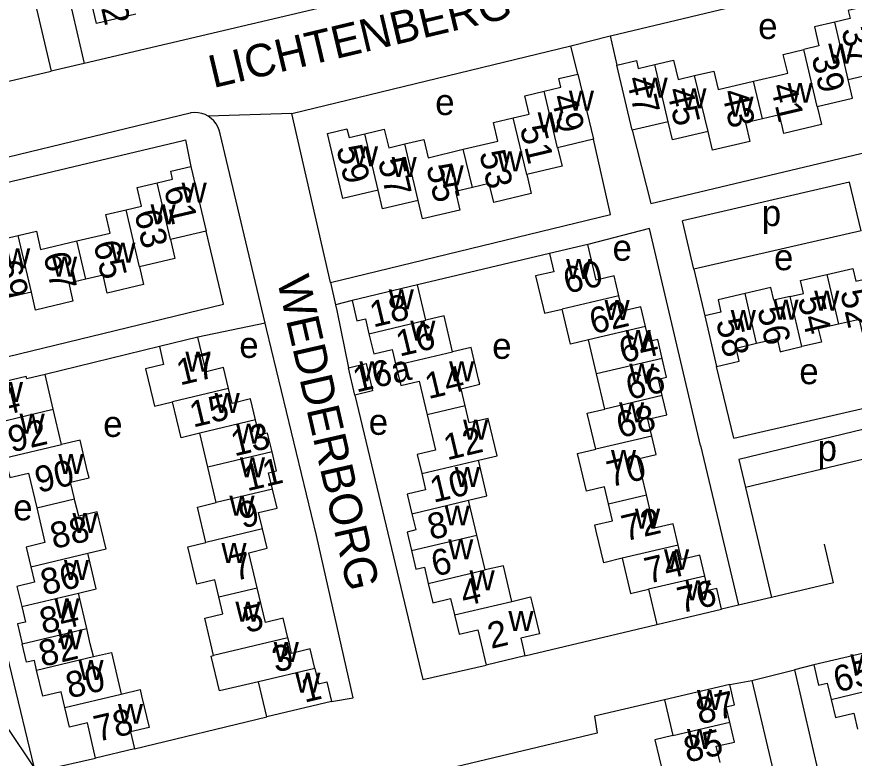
# Model space of a CAD drawing. Extents: x 157646 to 159241, y 379213 to 381217.
# Drawn here: x 158882.3 to 159011, y 380482.4 to 380596.4 of the extents above; entities that cross this region are included whole.
import ezdxf

# ---------------------------------------------------------------- set-up
doc = ezdxf.new("R2010")
doc.units = 0
for name, color, linetype in [('BLT_Basislijn', 7, 'Continuous'), ('BLT_Bebouwing', 7, 'Continuous'), ('BLT_Centroide', 7, 'Continuous'), ('BLT_Huisnummer', 7, 'Continuous'), ('BLT_Huisnummer_ tussenligend', 7, 'Continuous'), ('BLT_Onderverdeling_panden', 7, 'Continuous'), ('BLT_Straatnaam', 7, 'Continuous'), ('BLT_Vlakafsluiter', 7, 'Continuous')]:
    doc.layers.add(name, color=color, linetype=linetype)

msp = doc.modelspace()

# ---------------------------------------------------------------- linework, layer by layer
at = {"layer": 'BLT_Basislijn'}
for p, q in [((158877.56, 380630.67), (158887.56, 380588.05)), ((158890.7, 380597.66), (158892.65, 380589.24)), ((158931.2, 380598.31), (158892.65, 380589.24)), ((158967.46, 380591.96), (158973.51, 380593.48)), ((158973.51, 380593.48), (158974.53, 380588.98)), ((158968.54, 380587.61), (158967.46, 380591.96)), ((158892.65, 380589.24), (158887.56, 380588.05)), ((158865.01, 380582.73), (158887.56, 380588.05)), ((158908.94, 380581.61), (158855.86, 380568.7)), ((158920.46, 380549.28), (158913.52, 380578.44)), ((158908.19, 380577.48), (158909.04, 380573.42)), ((159010.31, 380570.97), (158984.61, 380565.02)), ((159012.09, 380563.48), (159010.31, 380570.97)), ((158986.36, 380557.62), (158984.61, 380565.02)), ((158964.16, 380560.01), (158943.87, 380555.18)), ((158930.51, 380555.55), (158931.28, 380552.13)), ((158933.81, 380552.79), (158931.28, 380552.13)), ((158920.46, 380549.28), (158910.12, 380547.13)), ((158904.19, 380545.72), (158886.63, 380541.42)), ((158992.48, 380531.61), (158989.86, 380542.66)), ((159017.31, 380534.13), (158993.25, 380528.36)), ((158987.39, 380530.49), (158993.2, 380505.92)), ((159018.36, 380529.81), (158994.28, 380524.03)), ((158993.25, 380528.36), (158994.28, 380524.03)), ((158994.28, 380524.03), (158998.29, 380507.12)), ((159007.83, 380509.38), (159006.42, 380515.34)), ((158993.2, 380505.92), (158990.63, 380505.31)), ((158960.4, 380498.13), (158980.68, 380502.96)), ((158944.72, 380494.53), (158954.44, 380496.71)), ((159004.81, 380496.74), (159001.81, 380495.97)), ((158995.27, 380494.34), (159001.81, 380495.97)), ((159001.81, 380495.97), (159010.79, 380457.61)), ((158991.88, 380493.75), (158995.27, 380494.34)), ((158995.27, 380494.34), (159004.29, 380456.24)), ((158900.37, 380483.84), (158920.71, 380488.74))]:
    msp.add_line(p, q, dxfattribs=at)
for points in [[(158973.51, 380593.48), (158973.74, 380593.53), (159014.59, 380603.35)], [(158976.89, 380578.97), (158979.77, 380567.69), (159056.36, 380585.97), (159053.88, 380597.08)], [(158924.54, 380581.53), (158967.46, 380591.96)], [(158911.72, 380581.12), (158911.23, 380581.38), (158910.71, 380581.56), (158910.16, 380581.66), (158909.61, 380581.69), (158909.05, 380581.63), (158908.94, 380581.61)], [(158913.52, 380578.44), (158913.4, 380578.98), (158913.19, 380579.5), (158912.92, 380579.98), (158912.58, 380580.42), (158912.18, 380580.8), (158911.72, 380581.12)], [(158930.51, 380555.55), (158924.54, 380581.53)], [(158838.2, 380560.85), (158907.85, 380577.41), (158908.19, 380577.48)], [(158930.51, 380555.55), (158973.55, 380566), (158970.92, 380577.58)], [(158987.39, 380530.49), (158979.54, 380563.84), (158970.05, 380561.41)], [(158865.95, 380540.53), (158914.06, 380552.25), (158911.37, 380563.45)], [(159012.09, 380563.48), (158986.36, 380557.62)], [(158986.36, 380557.62), (158988.06, 380550.41)], [(158931.28, 380552.13), (158931.48, 380551.25), (158933.26, 380542.46)], [(158930.66, 380491.12), (158933.99, 380491.67), (158928.35, 380516.64), (158920.66, 380548.44), (158920.46, 380549.28)], [(158934.26, 380538.23), (158944.72, 380494.53)], [(158992.48, 380531.61), (159016.74, 380537.19), (159018.05, 380537.49)], [(158877.97, 380509.59), (158884.88, 380481.07)], [(159007.83, 380509.38), (158998.29, 380507.12)], [(158998.29, 380507.12), (158993.2, 380505.92)], [(158884.88, 380481.07), (158872.72, 380499.22)], [(158981.85, 380491.39), (158971.06, 380488.87), (158971.5, 380486.26), (158925.77, 380475.35), (158905.24, 380470.64), (158904.26, 380470.56), (158903.54, 380472.61), (158902.77, 380472.58), (158881.56, 380467.45)], [(158884.88, 380481.07), (158885.27, 380480.69), (158886.62, 380480.68), (158894.4, 380482.43)]]:
    msp.add_lwpolyline(points, dxfattribs=at)
at = {"layer": 'BLT_Bebouwing'}
for p, q in [((158976.89, 380578.97), (158974.53, 380588.98)), ((158968.54, 380587.61), (158970.92, 380577.58)), ((159010.1, 380586.76), (159015.43, 380588.01)), ((158982.41, 380580.27), (158976.89, 380578.97)), ((158970.92, 380577.58), (158965.42, 380576.28)), ((158909.04, 380573.42), (158911.37, 380563.45)), ((158911.37, 380563.45), (158905.89, 380562.16)), ((158970.05, 380561.41), (158964.16, 380560.01)), ((158943.87, 380555.18), (158933.81, 380552.79)), ((158945.16, 380549.75), (158943.87, 380555.18)), ((158988.06, 380550.41), (158989.86, 380542.66)), ((158910.12, 380547.13), (158904.19, 380545.72)), ((158971.4, 380541.5), (158970.16, 380546.72)), ((158934.26, 380538.23), (158933.26, 380542.46)), ((158887.88, 380536.08), (158886.63, 380541.42)), ((158972.68, 380536.1), (158971.4, 380541.5)), ((158911.64, 380527.15), (158910.39, 380532.37)), ((158912.94, 380521.71), (158911.64, 380527.15)), ((158953.02, 380516.71), (158951.74, 380522.08)), ((158954.29, 380511.35), (158953.02, 380516.71)), ((158979.4, 380508.38), (158980.68, 380502.96)), ((158893.03, 380502.34), (158891.74, 380507.79)), ((158980.68, 380502.96), (158990.63, 380505.31)), ((158960.4, 380498.13), (158954.44, 380496.71)), ((159014.74, 380499.09), (159004.81, 380496.74)), ((158920.71, 380488.74), (158919.42, 380494.13)), ((158991.88, 380493.75), (158981.85, 380491.39)), ((158930.66, 380491.12), (158920.71, 380488.74)), ((158981.85, 380491.39), (158983.14, 380485.9)), ((158900.37, 380483.84), (158894.4, 380482.43))]:
    msp.add_line(p, q, dxfattribs=at)
for points in [[(158900.58, 380596.82), (158894.54, 380595.38), (158893.82, 380598.4), (158890.7, 380597.66)], [(159013.07, 380598.07), (159010.09, 380597.37), (159010.38, 380596.15), (159008.02, 380595.59)], [(159008.02, 380595.59), (159004.89, 380594.86), (159005.58, 380591.93), (159003.26, 380591.38)], [(158995.54, 380586.52), (159000, 380587.57), (159000.79, 380587.75), (159000.11, 380590.64), (159003.26, 380591.38)], [(158974.53, 380588.98), (158977.53, 380589.69), (158977.82, 380588.48), (158980.34, 380589.07)], [(158980.34, 380589.07), (158983.24, 380589.75), (158983.94, 380586.78), (158986.46, 380587.37)], [(158963.36, 380584.98), (158965.9, 380585.58), (158965.59, 380586.91), (158968.54, 380587.61)], [(158986.46, 380587.37), (158989.41, 380588.07), (158990.08, 380585.23), (158995.54, 380586.52)], [(159005.32, 380582.62), (159010.77, 380583.91), (159010.1, 380586.76)], [(158958.6, 380580.88), (158961.05, 380581.46), (158960.38, 380584.27), (158963.36, 380584.98)], [(159005.32, 380582.62), (159005.97, 380579.85), (159000.18, 380578.49), (158999.98, 380579.38), (158999.52, 380581.33), (158996.9, 380580.71)], [(158950.92, 380576.04), (158956.23, 380577.29), (158955.55, 380580.15), (158958.6, 380580.88)], [(158996.9, 380580.71), (158994.28, 380580.09), (158994.95, 380577.24), (158989.22, 380575.89), (158988.54, 380578.77)], [(158937.84, 380569.76), (158932.4, 380568.47), (158930.03, 380578.48), (158933.03, 380579.19), (158933.35, 380577.86), (158935.79, 380578.43)], [(158935.79, 380578.43), (158938.77, 380579.14), (158939.45, 380576.29), (158941.93, 380576.87)], [(158988.54, 380578.77), (158983.06, 380577.48), (158982.41, 380580.27)], [(158941.93, 380576.87), (158944.84, 380577.56), (158945.5, 380574.75), (158950.92, 380576.04)], [(158965.42, 380576.28), (158966.09, 380573.45), (158960.66, 380572.16)], [(158903.85, 380570.9), (158906.22, 380571.46), (158905.93, 380572.7), (158909.04, 380573.42)], [(158960.66, 380572.16), (158961.35, 380569.23), (158955.6, 380567.87), (158954.91, 380570.79), (158952.31, 380570.18)], [(158899.07, 380566.75), (158901.45, 380567.31), (158900.77, 380570.18), (158903.85, 380570.9)], [(158952.31, 380570.18), (158949.71, 380569.56), (158950.39, 380566.69), (158944.66, 380565.34), (158943.99, 380568.17)], [(158943.99, 380568.17), (158938.52, 380566.88), (158937.84, 380569.76)], [(158891.52, 380561.94), (158896.65, 380563.15), (158895.98, 380566.03), (158899.07, 380566.75)], [(158876.43, 380564.33), (158879.16, 380564.97), (158879.81, 380562.15), (158882.49, 380562.78)], [(158882.49, 380562.78), (158885.28, 380563.43), (158885.94, 380560.64), (158891.52, 380561.94)], [(158905.89, 380562.16), (158906.57, 380559.25), (158901.12, 380557.97)], [(158974.81, 380553.53), (158974.09, 380556.59), (158971.34, 380555.93), (158970.05, 380561.41)], [(158964.16, 380560.01), (158964.82, 380557.22), (158962.04, 380556.56), (158963.19, 380551.69), (158963.39, 380550.83), (158966.13, 380551.48)], [(158901.12, 380557.97), (158901.76, 380555.24), (158896.18, 380553.93), (158895.54, 380556.69), (158892.9, 380556.07)], [(159006.79, 380556.8), (159010.81, 380557.73), (159011.27, 380555.77), (159013.76, 380556.35)], [(158892.9, 380556.07), (158890.26, 380555.46), (158890.91, 380552.67), (158885.17, 380551.32), (158884.52, 380554.08)], [(159001.17, 380553.42), (159003.22, 380553.89), (159002.76, 380555.87), (159006.79, 380556.8)], [(158884.52, 380554.08), (158879.12, 380552.82), (158878.47, 380555.62)], [(159001.17, 380553.42), (159000, 380553.15), (158998.63, 380552.83), (158998.17, 380554.79), (158994.23, 380553.87)], [(158978.95, 380548.8), (158978.23, 380551.81), (158975.38, 380551.13), (158974.81, 380553.53)], [(158994.23, 380553.87), (158990.08, 380552.9), (158990.53, 380550.99), (158988.06, 380550.41)], [(158933.81, 380552.79), (158934.55, 380549.68), (158935.86, 380549.99), (158936.41, 380547.67)], [(158970.16, 380546.72), (158967.41, 380546.07), (158966.13, 380551.48)], [(158949.27, 380544.9), (158947.96, 380550.41), (158945.16, 380549.75)], [(159015.54, 380548.65), (159012.26, 380547.89), (159011.8, 380549.88), (159008.57, 380549.13)], [(158981.49, 380543.89), (158980.8, 380546.79), (158979.49, 380546.48), (158978.95, 380548.8)], [(159008.57, 380549.13), (159005.49, 380548.42), (159005.96, 380546.4), (159002.98, 380545.7)], [(158914.83, 380539.25), (158914.06, 380542.48), (158911.39, 380541.84), (158910.12, 380547.13)], [(158936.41, 380547.67), (158937.15, 380544.58), (158939.98, 380545.26), (158940.55, 380542.83)], [(158996.01, 380546.22), (158999.18, 380546.96), (158999.65, 380544.92), (159000, 380545), (159002.98, 380545.7)], [(158904.19, 380545.72), (158904.85, 380542.95), (158902.06, 380542.28), (158903.22, 380537.42), (158903.43, 380536.53), (158906.21, 380537.19)], [(158989.86, 380542.66), (158993.32, 380543.47), (158992.85, 380545.48), (158996.01, 380546.22)], [(158951.2, 380536.59), (158950.57, 380539.22), (158953.45, 380539.9), (158953.26, 380540.71), (158952.1, 380545.57), (158949.27, 380544.9)], [(158933.26, 380542.46), (158935.98, 380543.1), (158936.98, 380538.88), (158934.26, 380538.23)], [(158981.51, 380538.19), (158980.92, 380540.69), (158982.17, 380540.99), (158981.49, 380543.89)], [(158940.55, 380542.83), (158941.29, 380539.72), (158944.12, 380540.39), (158945.35, 380535.2)], [(158886.63, 380541.42), (158883.81, 380540.76), (158883.73, 380541.08), (158873.59, 380538.7)], [(158918.99, 380534.43), (158918.22, 380537.65), (158915.37, 380536.97), (158914.83, 380539.25)], [(158979.91, 380531.94), (158979.3, 380534.53), (158982.21, 380535.22), (158981.51, 380538.19)], [(158910.39, 380532.37), (158907.52, 380531.69), (158906.21, 380537.19)], [(158953.23, 380528.23), (158956.1, 380528.91), (158954.73, 380534.66), (158951.82, 380533.96), (158951.2, 380536.59)], [(158889.17, 380530.62), (158887.88, 380536.08)], [(158971.29, 380529.91), (158969.98, 380535.46), (158972.68, 380536.1)], [(158921.51, 380529.5), (158920.81, 380532.41), (158919.54, 380532.11), (158918.99, 380534.43)], [(158945.35, 380535.2), (158946.64, 380529.78), (158943.83, 380529.11), (158944.53, 380526.16)], [(158979.07, 380522.91), (158977.76, 380528.42), (158980.58, 380529.09), (158979.91, 380531.94)], [(158891.15, 380522.28), (158890.55, 380524.84), (158893.39, 380525.52), (158893.17, 380526.43), (158892.02, 380531.29), (158889.17, 380530.62)], [(158921.58, 380523.77), (158920.98, 380526.3), (158922.2, 380526.59), (158921.51, 380529.5)], [(158973.25, 380521.54), (158972.63, 380524.14), (158969.84, 380523.48), (158968.47, 380529.24), (158971.29, 380529.91)], [(158880.49, 380528.57), (158881.2, 380525.56), (158884.08, 380526.24), (158885.34, 380520.91)], [(158951.74, 380522.08), (158954.54, 380522.74), (158953.23, 380528.23)], [(158944.53, 380526.16), (158945.12, 380523.69), (158942.3, 380523.02), (158943.02, 380520)], [(158920.05, 380517.67), (158919.45, 380520.18), (158922.28, 380520.85), (158921.58, 380523.77)], [(158983.93, 380515.18), (158983.16, 380518.44), (158980.28, 380517.76), (158979.07, 380522.91)], [(158893.18, 380513.92), (158895.99, 380514.58), (158895.95, 380514.74), (158894.65, 380520.27), (158891.79, 380519.6), (158891.22, 380521.99), (158891.15, 380522.28)], [(158911.33, 380515.59), (158910.03, 380521.02), (158912.94, 380521.71)], [(158975.32, 380513.14), (158972.5, 380512.47), (158971.35, 380517.34), (158971.13, 380518.29), (158973.86, 380518.93), (158973.25, 380521.54)], [(158885.34, 380520.91), (158886.61, 380515.57), (158883.71, 380514.88), (158884.43, 380511.85)], [(158943.02, 380520), (158943.61, 380517.5), (158942.28, 380517.18), (158942.96, 380514.32)], [(158919.21, 380508.61), (158917.93, 380514), (158920.77, 380514.68), (158920.05, 380517.67)], [(158913.33, 380507.21), (158912.7, 380509.81), (158909.96, 380509.16), (158908.58, 380514.93), (158911.33, 380515.59)], [(158988.03, 380510.42), (158987.28, 380513.62), (158984.46, 380512.95), (158983.93, 380515.18)], [(158891.74, 380507.79), (158894.47, 380508.43), (158893.18, 380513.92)], [(158942.96, 380514.32), (158943.64, 380511.46), (158944.94, 380511.77), (158945.54, 380509.27)], [(158975.32, 380513.14), (158976.6, 380507.71), (158979.4, 380508.38)], [(158884.43, 380511.85), (158884.99, 380509.46), (158882.3, 380508.83), (158883.04, 380505.74)], [(158958.39, 380506.52), (158957.09, 380512.01), (158954.29, 380511.35)], [(158990.63, 380505.31), (158989.88, 380508.5), (158988.56, 380508.19), (158988.03, 380510.42)], [(158923.96, 380500.93), (158923.24, 380503.95), (158920.49, 380503.29), (158919.21, 380508.61)], [(158945.54, 380509.27), (158946.24, 380506.3), (158948.97, 380506.95), (158949.57, 380504.43)], [(158912.53, 380498.2), (158912.11, 380500.01), (158911.38, 380503.07), (158911.18, 380503.94), (158913.95, 380504.6), (158913.33, 380507.21)], [(158958.39, 380506.52), (158961.26, 380507.2), (158961.45, 380506.38), (158962.61, 380501.52), (158959.77, 380500.84), (158959.97, 380500), (158960.4, 380498.13)], [(158883.04, 380505.74), (158883.6, 380503.34), (158882.37, 380503.05), (158883.09, 380500)], [(158949.57, 380504.43), (158950.27, 380501.47), (158953.15, 380502.15), (158953.66, 380500), (158954.44, 380496.71)], [(158894.06, 380498.02), (158893.58, 380500), (158893.03, 380502.34)], [(158928.1, 380496.2), (158927.38, 380499.23), (158924.53, 380498.53), (158924.18, 380500.01), (158923.96, 380500.93)], [(158885.33, 380495.95), (158884.98, 380497.44), (158883.76, 380497.16), (158883.09, 380500)], [(158894.06, 380498.02), (158896.82, 380498.67), (158898.32, 380492.27)], [(158919.42, 380494.13), (158913.45, 380492.75), (158912.18, 380498.12), (158912.53, 380498.2)], [(159004.81, 380496.74), (159005.54, 380493.64), (159006.86, 380493.95), (159007.45, 380491.45)], [(158889.65, 380490.22), (158889.09, 380492.6), (158886.28, 380491.94), (158885.33, 380495.95)], [(158928.1, 380496.2), (158928.66, 380493.83), (158929.94, 380494.14), (158930.66, 380491.12)], [(158898.32, 380492.27), (158901.24, 380492.96), (158901.47, 380492.02), (158902.61, 380487.15), (158899.75, 380486.47), (158900.37, 380483.84)], [(158991.9, 380487.96), (158991.35, 380490.32), (158992.62, 380490.61), (158991.88, 380493.75)], [(159007.45, 380491.45), (159008.11, 380488.67), (159010.95, 380489.34), (159011.54, 380486.86)], [(158894.4, 380482.43), (158893.13, 380487.82), (158890.37, 380487.17), (158889.65, 380490.22)], [(158990.39, 380481.75), (158989.8, 380484.23), (158992.63, 380484.89), (158991.9, 380487.96)], [(158983.14, 380485.9), (158980.38, 380485.24), (158981.69, 380479.7)]]:
    msp.add_lwpolyline(points, dxfattribs=at)
at = {"layer": 'BLT_Onderverdeling_panden'}
for p, q in [((159010.1, 380586.76), (159008.02, 380595.59)), ((159005.32, 380582.62), (159003.26, 380591.38)), ((158982.41, 380580.27), (158980.34, 380589.07)), ((158988.54, 380578.77), (158986.46, 380587.37)), ((158996.9, 380580.71), (158995.54, 380586.52)), ((158965.42, 380576.28), (158963.36, 380584.98)), ((158960.66, 380572.16), (158958.6, 380580.88)), ((158937.84, 380569.76), (158935.79, 380578.43)), ((158943.99, 380568.17), (158941.93, 380576.87)), ((158952.31, 380570.18), (158950.92, 380576.04)), ((158905.89, 380562.16), (158903.85, 380570.9)), ((158901.12, 380557.97), (158899.07, 380566.75)), ((158884.52, 380554.08), (158882.49, 380562.78)), ((158892.9, 380556.07), (158891.52, 380561.94)), ((159006.79, 380556.8), (159008.57, 380549.13)), ((158974.81, 380553.53), (158966.13, 380551.48)), ((158996.01, 380546.22), (158994.23, 380553.87)), ((159002.98, 380545.7), (159001.17, 380553.42)), ((158936.41, 380547.67), (158945.16, 380549.75)), ((158978.95, 380548.8), (158970.16, 380546.72)), ((158940.55, 380542.83), (158949.27, 380544.9)), ((158981.49, 380543.89), (158971.4, 380541.5)), ((158914.83, 380539.25), (158906.21, 380537.19)), ((158981.51, 380538.19), (158972.68, 380536.1)), ((158951.2, 380536.59), (158945.35, 380535.2)), ((158876.38, 380533.36), (158887.88, 380536.08)), ((158918.99, 380534.43), (158910.39, 380532.37)), ((158979.91, 380531.94), (158971.29, 380529.91)), ((158880.49, 380528.57), (158889.17, 380530.62)), ((158921.51, 380529.5), (158911.64, 380527.15)), ((158944.53, 380526.16), (158953.23, 380528.23)), ((158921.58, 380523.77), (158912.94, 380521.71)), ((158973.25, 380521.54), (158979.07, 380522.91)), ((158885.34, 380520.91), (158891.15, 380522.28)), ((158943.02, 380520), (158951.74, 380522.08)), ((158920.05, 380517.67), (158911.33, 380515.59)), ((158942.96, 380514.32), (158953.02, 380516.71)), ((158983.93, 380515.18), (158975.32, 380513.14)), ((158884.43, 380511.85), (158893.18, 380513.92)), ((158945.54, 380509.27), (158954.29, 380511.35)), ((158988.03, 380510.42), (158979.4, 380508.38)), ((158913.33, 380507.21), (158919.21, 380508.61)), ((158883.04, 380505.74), (158891.74, 380507.79)), ((158949.57, 380504.43), (158958.39, 380506.52)), ((158883.09, 380500), (158893.03, 380502.34)), ((158923.96, 380500.93), (158912.53, 380498.2)), ((158885.33, 380495.95), (158894.06, 380498.02)), ((158928.1, 380496.2), (158919.42, 380494.13)), ((159007.45, 380491.45), (159016.07, 380493.49)), ((158889.65, 380490.22), (158898.32, 380492.27)), ((158983.14, 380485.9), (158991.9, 380487.96))]:
    msp.add_line(p, q, dxfattribs=at)
at = {"layer": 'BLT_Vlakafsluiter'}
msp.add_line((158924.54, 380581.53), (158911.72, 380581.12), dxfattribs=at)

# ---------------------------------------------------------------- texts
at = {"layer": 'BLT_Centroide'}
for s, p in [('e', (158996.25, 380593)), ('w', (159007.02, 380589.19)), ('w', (158978.47, 380583.98)), ('w', (159000.75, 380583.19)), ('e', (158946.6, 380581.31)), ('w', (158967.14, 380581.98)), ('w', (158984.44, 380582.36)), ('w', (158991.67, 380581.05)), ('w', (158962.34, 380578.66)), ('w', (158933.94, 380573.42)), ('w', (158956.14, 380572.64)), ('w', (158939.89, 380571.8)), ('w', (158947.12, 380570.52)), ('w', (158907.61, 380567.83)), ('w', (158902.83, 380564.52)), ('p', (158996.8, 380564.24)), ('w', (158896.64, 380558.59)), ('e', (158973.86, 380558.91)), ('w', (158880.47, 380557.72)), ('e', (158998.68, 380557.45)), ('w', (158887.69, 380556.47)), ('w', (158966.72, 380556.12)), ('w', (158939.45, 380551.44)), ('w', (159004.86, 380551.25)), ('w', (158972.62, 380549.81)), ('w', (158998.58, 380549.84)), ('w', (158992.03, 380548.25)), ('w', (158942.76, 380546.62)), ('w', (158975.86, 380545.16)), ('e', (158916.48, 380543.96)), ('e', (158955.36, 380543.82)), ('w', (158908.19, 380541.84)), ('w', (158934.96, 380540.35)), ('w', (158948.73, 380540.38)), ('w', (158976.42, 380540)), ('e', (159002.57, 380539.92)), ('w', (158879.36, 380537.16)), ('w', (158912.68, 380535.47)), ('w', (158974.86, 380534.06)), ('w', (158882.7, 380532.31)), ('e', (158895.56, 380531.81)), ('e', (158936.38, 380532.13)), ('w', (158950.89, 380531.38)), ('w', (158915.98, 380530.78)), ('p', (159005.39, 380528.09)), ('w', (158888.68, 380526.09)), ('w', (158973.61, 380526.75)), ('w', (158916.57, 380525.59)), ('w', (158949.61, 380524.12)), ('w', (158914.96, 380519.69)), ('e', (158881.73, 380518.98)), ('w', (158948.05, 380518.19)), ('w', (158890.83, 380517.06)), ('w', (158977.3, 380517.69)), ('w', (158948.59, 380513)), ('w', (158913.73, 380512.44)), ('w', (158981.76, 380511.44)), ('w', (158889.52, 380509.81)), ('w', (158951.88, 380508.22)), ('w', (158985.05, 380506.69)), ('w', (158888.06, 380503.91)), ('w', (158915.88, 380503.41)), ('w', (158957.85, 380501.97)), ('w', (158888.54, 380499.16)), ('w', (158921.77, 380497.19)), ('w', (159010.41, 380495.28)), ('w', (158891.75, 380494.44)), ('w', (158925.08, 380492.47)), ('w', (158986.84, 380489.81)), ('w', (158897.82, 380487.69)), ('w', (158985.3, 380483.84))]:
    msp.add_text(s, height=4, dxfattribs=at).set_placement(p)
at = {"layer": 'BLT_Huisnummer'}
for s, rotation, p in [('62', 283.3942, (158894.52, 380600.68)), ('37', 283.2509, (159009.01, 380594.41)), ('47', 283.2509, (158975.95, 380586.88)), ('41', 283.2509, (158998.11, 380585.75)), ('49', 283.315, (158964.38, 380584.09)), ('59', 283.3094, (158931.38, 380576.25)), ('53', 283.3026, (158953.35, 380575.47)), ('61', 283.1845, (158904.87, 380570.03)), ('65', 283.1845, (158894.03, 380561.58)), ('69', 283.1845, (158878.94, 380558.56)), ('60', 13.2903, (158966.83, 380553.81)), ('18', 13.376, (158937.07, 380548.63)), ('52', 283.0479, (159008.83, 380554.1)), ('58', 283.1382, (158989.74, 380549.6)), ('64', 13.3017, (158975.41, 380543.12)), ('17', 13.4322, (158907.36, 380539.71)), ('16a', 13.3086, (158934.48, 380538.62)), ('14', 13.376, (158945.55, 380537.61)), ('94', 13.2523, (158877.29, 380534.38)), ('68', 13.3017, (158974.99, 380531.62)), ('13', 13.4322, (158915.72, 380528.8)), ('90', 13.2523, (158885.59, 380523.18)), ('10', 13.376, (158946.33, 380521.67)), ('9', 13.4322, (158916.94, 380517.72)), ('72', 13.3017, (158975.77, 380515.73)), ('6', 13.376, (158946.53, 380510.31)), ('86', 13.2523, (158886.46, 380507.43)), ('76', 13.3017, (158984.34, 380504.67)), ('5', 13.4322, (158917.62, 380501.64)), ('2', 13.376, (158955.18, 380499.2)), ('82', 13.2523, (158886.18, 380496.42)), ('65', 13.343, (159008.35, 380492.5)), ('1', 13.4322, (158926.5, 380490.92)), ('87', 13.2507, (158987.22, 380487.57)), ('78', 13.2523, (158894.65, 380484.9))]:
    msp.add_text(s, height=4, rotation=rotation, dxfattribs=at).set_placement(p)
at = {"layer": 'BLT_Huisnummer_ tussenligend'}
for s, rotation, p in [('39', 283.2509, (159004.42, 380590.25)), ('45', 283.2509, (158982.15, 380585.15)), ('43', 283.2509, (158990.6, 380584.85)), ('51', 283.315, (158959.59, 380579.35)), ('57', 283.3026, (158937.78, 380574.29)), ('55', 283.3026, (158945.2, 380573.39)), ('63', 283.1845, (158900.32, 380566.32)), ('67', 283.1845, (158886.32, 380559.82)), ('54', 283.0479, (159002.31, 380553.08)), ('62', 13.2903, (158970.85, 380547.58)), ('56', 283.0479, (158996.09, 380551.45)), ('16', 13.376, (158941.11, 380544.14)), ('66', 13.3017, (158976.45, 380537.48)), ('15', 13.4322, (158909.38, 380533.24)), ('92', 13.2523, (158881.45, 380529.41)), ('12', 13.376, (158948.42, 380528.2)), ('70', 13.3017, (158973.5, 380524.06)), ('11', 13.4322, (158917.68, 380523.44)), ('8', 13.376, (158945.95, 380515.94)), ('88', 13.2523, (158887.95, 380514.55)), ('7', 13.4322, (158915.83, 380509.64)), ('74', 13.3017, (158979.31, 380509.21)), ('4', 13.376, (158951.02, 380505.72)), ('84', 13.2523, (158886.32, 380501.46)), ('3', 13.4322, (158922.06, 380495.56)), ('80', 13.2523, (158890.34, 380491.57)), ('85', 13.2555, (158985.33, 380481.7))]:
    msp.add_text(s, height=4, rotation=rotation, dxfattribs=at).set_placement(p)
at = {"layer": 'BLT_Straatnaam'}
for s, height, rotation, p in [('LICHTENBERG', 4.9999, 13.3628, (158912.47, 380585.44)), ('WEDDERBORG', 5, 282.861, (158922.24, 380555.99))]:
    msp.add_text(s, height=height, rotation=rotation, dxfattribs=at).set_placement(p)

doc.saveas('drawing.dxf')
